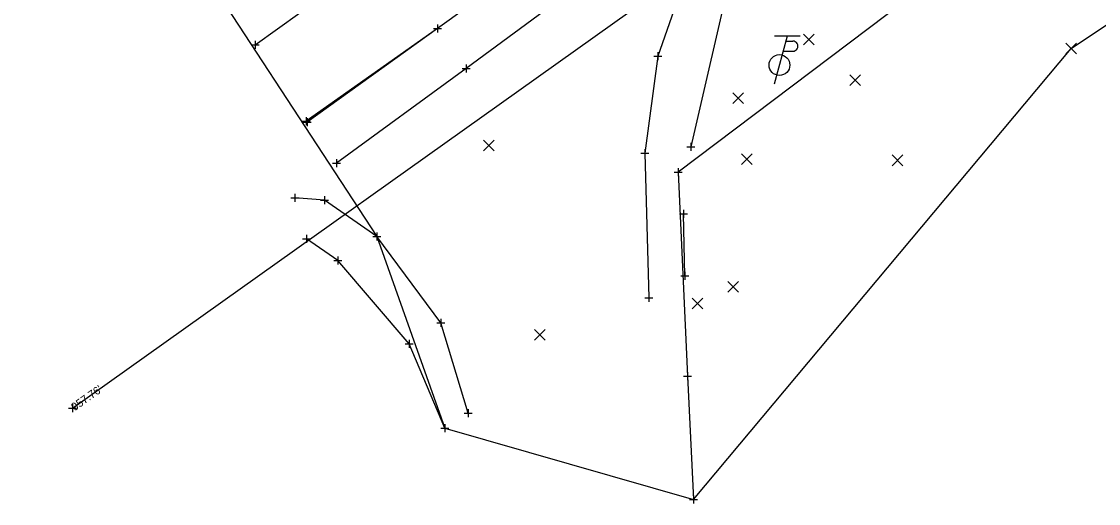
# Model space of a CAD drawing. Extents: x -4 to 139204, y -4 to 477121.
# Drawn here: x 138901 to 139035.5, y 476831.2 to 476891.5 of the extents above; entities that cross this region are included whole.
import ezdxf

# ---------------------------------------------------------------- set-up
doc = ezdxf.new("R2010")
doc.units = 0
for name, color, linetype in [('DR_X_Ditch', 7, 'Continuous'), ('DR_X_Storm_Sewer', 7, 'Continuous'), ('GE_X_Alignment', 7, 'Continuous'), ('GE_X_Alignment_100_Bearings', 7, 'Continuous'), ('GE_X_Alignment_100_Cardinal_Points', 7, 'Continuous'), ('GE_X_Alignment_100_Distances', 7, 'Continuous'), ('PM_X_Edge_Line', 7, 'Continuous'), ('PM_X_Surveyed_Line', 7, 'Continuous'), ('PV_X_COP', 7, 'Continuous'), ('PV_X_Driveway', 7, 'Continuous'), ('PV_X_EOP', 7, 'Continuous'), ('PV_X_Shoulder', 7, 'Continuous'), ('RD_X_Fence', 7, 'Continuous'), ('SC_Scratch1', 7, 'Continuous'), ('SV_X_Terrain_Boundary', 7, 'Continuous')]:
    doc.layers.add(name, color=color, linetype=linetype)

msp = doc.modelspace()

# ---------------------------------------------------------------- linework, layer by layer
at = {"layer": 'DR_X_Ditch'}
msp.add_lwpolyline([(138953.87, 476840.64), (138949.41, 476851.19), (138940.49, 476861.59), (138936.6, 476864.3)], dxfattribs=at)
at = {"layer": 'DR_X_Storm_Sewer'}
msp.add_line((138907.35, 476843.17), (139091.62, 476974.36), dxfattribs=at)
msp.add_line((138907.35, 476843.17), (139091.62, 476974.36), dxfattribs=at)
at = {"layer": 'GE_X_Alignment'}
for p, q in [((138998.68, 476888.54), (139000.02, 476889.88)), ((138998.68, 476889.88), (139000.02, 476888.54)), ((139031.43, 476887.41), (139032.76, 476888.74)), ((139031.43, 476888.74), (139032.76, 476887.41)), ((139004.47, 476883.48), (139005.8, 476884.81)), ((139004.47, 476884.81), (139005.8, 476883.48)), ((138989.84, 476881.23), (138991.18, 476882.57)), ((138989.84, 476882.57), (138991.18, 476881.23)), ((138958.69, 476875.3), (138960.03, 476876.63)), ((138958.69, 476876.63), (138960.03, 476875.3)), ((138990.94, 476873.61), (138992.27, 476874.94)), ((138990.94, 476874.94), (138992.27, 476873.61)), ((139009.74, 476873.45), (139011.07, 476874.79)), ((139009.74, 476874.79), (139011.07, 476873.45)), ((138989.21, 476857.63), (138990.54, 476858.96)), ((138989.21, 476858.96), (138990.54, 476857.63)), ((138984.75, 476855.57), (138986.09, 476856.91)), ((138984.75, 476856.91), (138986.09, 476855.57)), ((138965.07, 476851.66), (138966.4, 476852.99)), ((138965.07, 476852.99), (138966.4, 476851.66))]:
    msp.add_line(p, q, dxfattribs=at)
at = {"layer": 'GE_X_Alignment_100_Bearings'}
for p, q in [((138952.44, 476890.59), (138953.44, 476890.59)), ((138952.44, 476890.59), (138953.44, 476890.59)), ((138952.94, 476891.09), (138952.94, 476890.09)), ((138952.94, 476891.09), (138952.94, 476890.09)), ((138952.94, 476890.59), (138952.94, 476890.59)), ((138952.94, 476890.59), (138952.94, 476890.59)), ((138930.18, 476889.06), (138930.18, 476888.06)), ((138930.2, 476889.05), (138930.2, 476888.05)), ((138929.68, 476888.56), (138930.68, 476888.56)), ((138929.7, 476888.55), (138930.7, 476888.55)), ((138930.18, 476888.56), (138930.18, 476888.56)), ((138930.2, 476888.55), (138930.2, 476888.55)), ((138980.48, 476887.65), (138980.48, 476886.65)), ((138979.98, 476887.15), (138980.98, 476887.15)), ((138980.48, 476887.15), (138980.48, 476887.15)), ((138956.06, 476885.61), (138957.06, 476885.61)), ((138956.56, 476886.11), (138956.56, 476885.11)), ((138956.56, 476885.61), (138956.56, 476885.61)), ((138936.54, 476879.51), (138936.54, 476878.51)), ((138936.04, 476879.01), (138937.04, 476879.01)), ((138936.19, 476878.89), (138937.19, 476878.89)), ((138936.54, 476879.01), (138936.54, 476879.01)), ((138936.69, 476879.39), (138936.69, 476878.39)), ((138936.69, 476878.89), (138936.69, 476878.89)), ((138978.87, 476875.53), (138978.87, 476874.53)), ((138984.1, 476875.79), (138985.1, 476875.79)), ((138984.6, 476876.29), (138984.6, 476875.29)), ((138984.6, 476875.79), (138984.6, 476875.79)), ((138940.34, 476874.27), (138940.34, 476873.27)), ((138978.37, 476875.03), (138979.37, 476875.03)), ((138978.87, 476875.03), (138978.87, 476875.03)), ((138939.84, 476873.77), (138940.84, 476873.77)), ((138940.34, 476873.77), (138940.34, 476873.77)), ((138983.01, 476873.12), (138983.01, 476872.12)), ((138982.51, 476872.62), (138983.51, 476872.62)), ((138983.01, 476872.62), (138983.01, 476872.62)), ((138934.63, 476869.45), (138935.63, 476869.45)), ((138935.13, 476869.95), (138935.13, 476868.95)), ((138935.13, 476869.45), (138935.13, 476869.45)), ((138938.35, 476869.15), (138939.35, 476869.15)), ((138938.85, 476869.65), (138938.85, 476868.65)), ((138938.85, 476869.15), (138938.85, 476869.15)), ((138983.19, 476867.43), (138984.19, 476867.43)), ((138983.69, 476867.93), (138983.69, 476866.93)), ((138983.69, 476867.43), (138983.69, 476867.43)), ((138936.6, 476864.8), (138936.6, 476863.8)), ((138945.39, 476865.12), (138945.39, 476864.12)), ((138936.1, 476864.3), (138937.1, 476864.3)), ((138936.6, 476864.3), (138936.6, 476864.3)), ((138944.89, 476864.62), (138945.89, 476864.62)), ((138945.39, 476864.62), (138945.39, 476864.62)), ((138940.49, 476862.09), (138940.49, 476861.09)), ((138939.99, 476861.59), (138940.99, 476861.59)), ((138940.49, 476861.59), (138940.49, 476861.59)), ((138983.37, 476859.67), (138984.37, 476859.67)), ((138983.87, 476860.17), (138983.87, 476859.17)), ((138983.87, 476859.67), (138983.87, 476859.67)), ((138978.87, 476856.94), (138979.87, 476856.94)), ((138979.37, 476857.44), (138979.37, 476856.44)), ((138979.37, 476856.94), (138979.37, 476856.94)), ((138953.38, 476854.33), (138953.38, 476853.33)), ((138952.88, 476853.83), (138953.88, 476853.83)), ((138953.38, 476853.83), (138953.38, 476853.83)), ((138949.41, 476851.69), (138949.41, 476850.69)), ((138948.91, 476851.19), (138949.91, 476851.19)), ((138949.41, 476851.19), (138949.41, 476851.19)), ((138984.17, 476847.65), (138984.17, 476846.65)), ((138983.67, 476847.15), (138984.67, 476847.15)), ((138984.17, 476847.15), (138984.17, 476847.15)), ((138956.28, 476842.52), (138957.28, 476842.52)), ((138956.78, 476843.02), (138956.78, 476842.02)), ((138956.78, 476842.52), (138956.78, 476842.52)), ((138953.37, 476840.64), (138954.37, 476840.64)), ((138953.87, 476841.14), (138953.87, 476840.14)), ((138953.87, 476840.64), (138953.87, 476840.64)), ((138984.42, 476831.75), (138985.42, 476831.75)), ((138984.92, 476832.25), (138984.92, 476831.25)), ((138984.92, 476831.75), (138984.92, 476831.75))]:
    msp.add_line(p, q, dxfattribs=at)
at = {"layer": 'GE_X_Alignment_100_Cardinal_Points'}
for p, q in [((138996.64, 476889.62), (138995.03, 476883.62)), ((138998.24, 476889.62), (138995.04, 476889.62)), ((138996.48, 476889.02), (138997.33, 476889.02)), ((138996.13, 476887.74), (138997.33, 476887.74))]:
    msp.add_line(p, q, dxfattribs=at)
msp.add_circle((138995.67, 476886.02), 1.3, dxfattribs=at)
msp.add_arc((138997.34, 476888.38), 0.638, 268.8767, 91.1233, dxfattribs=at)
at = {"layer": 'GE_X_Alignment_100_Distances'}
for p, q in [((138906.85, 476843.17), (138907.85, 476843.17)), ((138907.35, 476843.67), (138907.35, 476842.67)), ((138907.35, 476843.17), (138907.35, 476843.17))]:
    msp.add_line(p, q, dxfattribs=at)
at = {"layer": 'PM_X_Edge_Line'}
msp.add_lwpolyline([(139119.98, 477018.53), (139108.07, 477008.29), (139096.43, 476998.56), (139075.62, 476981.79), (139057.89, 476968.01), (139018.12, 476938.02), (138977.72, 476908.35), (138952.94, 476890.59), (138936.69, 476878.89)], dxfattribs=at)
at = {"layer": 'PM_X_Surveyed_Line'}
msp.add_lwpolyline([(138930.18, 476888.56), (138972.01, 476918.56), (139012.49, 476948.2), (139029.81, 476961.23), (139052.08, 476978.04), (139073.56, 476995.35), (139089.17, 477007.92), (139110.85, 477026.03), (139111.35, 477026.74)], dxfattribs=at)
at = {"layer": 'PV_X_COP'}
msp.add_lwpolyline([(138930.2, 476888.55), (138972.01, 476918.56), (139012.49, 476948.2), (139029.81, 476961.23), (139052.08, 476978.04), (139073.56, 476995.35), (139089.17, 477007.92), (139110.85, 477026.03), (139129.38, 477042.53), (139155.72, 477066.27), (139171.58, 477080.9)], dxfattribs=at)
at = {"layer": 'PV_X_Driveway'}
for points in [[(138990.75, 476908.58), (138984.21, 476897.89), (138980.48, 476887.15), (138978.87, 476875.03), (138979.37, 476856.94)], [(138956.78, 476842.52), (138953.38, 476853.83), (138945.39, 476864.62), (138938.85, 476869.15), (138935.13, 476869.45)]]:
    msp.add_lwpolyline(points, dxfattribs=at)
at = {"layer": 'PV_X_EOP'}
msp.add_lwpolyline([(139119.99, 477018.51), (139108.07, 477008.29), (139096.43, 476998.56), (139075.62, 476981.79), (139057.89, 476968.01), (139018.12, 476938.02), (138977.72, 476908.35), (138952.94, 476890.59), (138936.54, 476879.01)], dxfattribs=at)
at = {"layer": 'PV_X_Shoulder'}
msp.add_lwpolyline([(139183.64, 477072.42), (139153.92, 477045.3), (139136.79, 477030.02), (139126.34, 477020.83), (139109.65, 477006.83), (139097.9, 476996.89), (139077.1, 476979.89), (139059.39, 476965.89), (139020.11, 476935.56), (139003.35, 476922.96), (138997.92, 476918.67), (138993.96, 476914.1), (138990.51, 476910.31), (138981.31, 476903.86), (138956.56, 476885.61), (138940.34, 476873.77)], dxfattribs=at)
at = {"layer": 'RD_X_Fence'}
for points in [[(139170.21, 476966.83), (139152.18, 476981.46), (139140.02, 476988.54), (139126.51, 476979.25), (139077.42, 476943.21), (139054.3, 476926.02), (139036.04, 476912.29), (139009.14, 476892.32), (138983.01, 476872.62), (138984.17, 476847.15), (138984.92, 476831.75)], [(138983.87, 476859.67), (138983.69, 476867.43)]]:
    msp.add_lwpolyline(points, dxfattribs=at)
at = {"layer": 'SC_Scratch1'}
msp.add_lwpolyline([(139071.87, 476964.68), (139042.72, 476944.31), (139020.96, 476928.9), (139008.81, 476916.16), (139005.38, 476912.98), (138998.45, 476910.11), (138989.77, 476898.22), (138984.6, 476875.79)], dxfattribs=at)
at = {"layer": 'SV_X_Terrain_Boundary'}
msp.add_lwpolyline([(138901, 476928.01), (138919.12, 476904.77), (138945.39, 476864.62), (138953.87, 476840.64), (138984.92, 476831.75), (139032.1, 476888.08), (139056.89, 476904.7)], dxfattribs=at)

# ---------------------------------------------------------------- texts
at = {"layer": 'SC_Scratch1'}
msp.add_text("957.76'", height=1, rotation=35.4496, dxfattribs=at).set_placement((138907.64, 476842.76))
msp.add_text("957.76'", height=1, rotation=35.4496, dxfattribs=at).set_placement((138907.64, 476842.76))

doc.saveas('drawing.dxf')
